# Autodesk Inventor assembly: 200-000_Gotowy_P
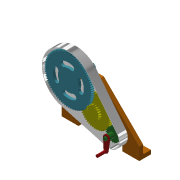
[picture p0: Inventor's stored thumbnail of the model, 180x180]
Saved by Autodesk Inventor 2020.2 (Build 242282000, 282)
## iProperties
Created: 2014-01
Part Number: 200-000_Gotowy_P
Document SubType Name: Assembly
Designer: F.Stasiak
Manager: www.cadconsulting.pl
Company: Fabian Stasiak CAD Consulting
Author: F.Stasiak
Subject: Zbiór ćwiczeń. Autodesk Inventor 2020. Kurs podstawowy
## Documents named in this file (9)
- C:\2020_Kurs_podstawowy\R6 Zespoły\Warsztat\Gotowe\200-000_Gotowy_P.iam
- C:\2020_Kurs_podstawowy\R6 Zespoły\Warsztat\Komponenty\200-001.ipt
- C:\2020_Kurs_podstawowy\R6 Zespoły\Warsztat\Komponenty\200-004.ipt
- C:\2020_Kurs_podstawowy\R6 Zespoły\Warsztat\Komponenty\200-003.ipt
- C:\2020_Kurs_podstawowy\R6 Zespoły\Warsztat\Komponenty\200-006.ipt
- C:\2020_Kurs_podstawowy\R6 Zespoły\Warsztat\Komponenty\200-007.ipt
- C:\2020_Kurs_podstawowy\R6 Zespoły\Warsztat\Komponenty\200-005.ipt
- C:\2020_Kurs_podstawowy\R6 Zespoły\Warsztat\Komponenty\200-002.ipt
- C:\2020_Kurs_podstawowy\R6 Zespoły\Warsztat\Komponenty\Obudowa.ipt
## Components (9 placed, 8 different names)
1. 200-001:1 — Obrotowe:1, Obrotowe:3, Obrotowe:5, Obrotowe:7, Obrotowe:8
2. 200-006:1 — NAPĘD, Obrotowe:1
3. 200-006:2 — Obrotowe:3, Obrotowe:4
4. 200-007:1 — Obrotowe:5, Obrotowe:6
5. Koło z=20 — NAPĘD, Sztywne:1
6. Koło z=20/51 — Obrotowe:4
7. Koło z=80 — Obrotowe:6
8. 200-005:1 — Sztywne:1
9. Obudowa:1 — Obrotowe:7, Obrotowe:8
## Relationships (9: RevoluteJoint 8, WeldJoint 1)
- NAPĘD [RevoluteJoint]: 200-006:1 ↔ Koło z=20
- Obrotowe:1 [RevoluteJoint]: 200-001:1 ↔ 200-006:1
- Sztywne:1 [WeldJoint]: Koło z=20 ↔ 200-005:1
- Obrotowe:3 [RevoluteJoint]: 200-001:1 ↔ 200-006:2
- Obrotowe:4 [RevoluteJoint]: 200-006:2 ↔ Koło z=20/51
- Obrotowe:5 [RevoluteJoint]: 200-001:1 ↔ 200-007:1
- Obrotowe:6 [RevoluteJoint]: 200-007:1 ↔ Koło z=80
- Obrotowe:7 [RevoluteJoint]: 200-001:1 ↔ Obudowa:1
- Obrotowe:8 [RevoluteJoint]: 200-001:1 ↔ Obudowa:1
